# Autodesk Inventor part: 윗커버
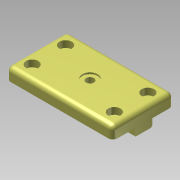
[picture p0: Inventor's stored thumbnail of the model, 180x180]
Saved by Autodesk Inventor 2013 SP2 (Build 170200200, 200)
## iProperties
Created: 2025-04
Part Number: 윗커버
Material: Generic
Document SubType Name: Modeling
Designer: i
Density: 1 g/cm^3
Author: i
변환 표준: STEP AP214IS
전처리기: Build: 200, Release: 2013 SP2 Update 6 - Date: Thu 07/17/2014
전송 단위: 밀리미터
불확실성: 0.01
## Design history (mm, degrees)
node "윗커버1"
node "솔리드1"
node "기준1"
